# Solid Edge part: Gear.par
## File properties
Author: Admin
Template: SEER_ExtSpurGear.par
Last saved by: Admin
Revision: 3
Application: Solid Edge
Density: 7833.000 kg/m^3
Accuracy: 0.990
SEER_Parameters: SEERSG2#ER#4#ER#0.349065850398866#ER#0.003#ER#0.032#ER#0#ER#0.001#ER#0#ER#1#ER#1.2#ER#0.8#ER#10000#ER#1#ER#1#ER#30#ER#120#ER#0.0024#ER#0.0064#ER#0.01#ER#0.014#ER#0#ER#0#ER#6#ER#1000#ER#104.71975511966#ER#104.71975511966#ER#9.54#ER#9.54#ER#0.92#ER#1#ER#1#ER#1#ER#1#ER#0#ER#0#ER#1#ER#0#ER#0#ER#1#ER#0#ER#0#ER#0.08#ER#0.08#ER#0.008#ER#0.008#ER#0.025#ER#0.025#ER#0#ER#1140#ER#605#ER#0#ER#1140#ER#390#ER#11#ER#SweptProtrusion_1#ER#Pattern_1#ER#SweptProtrusion_1#ER#Pattern_1#ER##ER#E:\Project\3D\SoccerBot\Hardware\Pinion.par#ER#0#ER#0#ER#ExtrudedProtrusion_4#ER#ExtrudedCutout_5#ER#ExtrudedProtrusion_4#ER#ExtrudedCutout_5#ER#0#ER#1#ER#0#ER#0#ER#False#ER#0
Username: Admin
Material: Steel
Face Style: Steel
Fill Style: ANSI32(Steel)
Virtual Style: Machined steel
Coef. of Thermal Exp: 1.3e-05
Thermal Conductivity: 32.0
Specific Heat: 481.0
Modulus of Elasticity: 199947953000.0
Poission's Ratio: 0.29
Yield Stress: 262000766.0
Ultimate Stress: 358527364.0
Elongation: 0.0
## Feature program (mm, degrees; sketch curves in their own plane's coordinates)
sketch for "unnamed Protrusion 1" plane through (0, 0, 0) normal (0, 0, 1) x-axis (1, 0, 0)
  circle centre (0, 0) radius 5.5775
extrude "unnamed Protrusion 1" add finite 10 along +normal
sketch for "unnamed Cutout 1" plane through (0, 0, 10) normal (0, 0, 1) x-axis (0, 1, 0)
extrude "unnamed Cutout 1" cut through along -normal
swept protrusion "SweptProtrusion_1"
pattern "unnamed Pattern 1" of "SweptProtrusion_1"
swept protrusion "unnamed SweptProtrusion 1"
swept protrusion "unnamed SweptProtrusion 2"
swept protrusion "unnamed SweptProtrusion 3"
swept protrusion "unnamed SweptProtrusion 4"
swept protrusion "unnamed SweptProtrusion 5"
swept protrusion "unnamed SweptProtrusion 6"
swept protrusion "unnamed SweptProtrusion 7"
swept protrusion "unnamed SweptProtrusion 8"
swept protrusion "unnamed SweptProtrusion 9"
swept protrusion "unnamed SweptProtrusion 10"
swept protrusion "unnamed SweptProtrusion 11"
swept protrusion "unnamed SweptProtrusion 12"
swept protrusion "unnamed SweptProtrusion 13"
swept protrusion "unnamed SweptProtrusion 14"
swept protrusion "unnamed SweptProtrusion 15"
swept protrusion "unnamed SweptProtrusion 16"
swept protrusion "unnamed SweptProtrusion 17"
swept protrusion "unnamed SweptProtrusion 18"
swept protrusion "unnamed SweptProtrusion 19"
swept protrusion "unnamed SweptProtrusion 20"
sketch for "ExtrudedProtrusion_5" plane through (0, 0.024, 0) normal (0, 0, -1) x-axis (1, 0, 0)
  circle centre (0, 0.024) radius 7.095
extrude "ExtrudedProtrusion_5" add finite 1 along +normal
sketch for "ExtrudedCutout_6" plane through (0, 0.024, 0) normal (0, 0, -1) x-axis (1, 0, 0)
  circle centre (0, 0.024) radius 1.2
extrude "ExtrudedCutout_6" cut finite 21.5926 symmetric
base feature "unnamed BaseFeature 1"
sketch for "ExtrudedProtrusion_4" plane through (0, 0, 0) normal (0, 0, 1) x-axis (1, 0, 0)
  circle centre (0, 0) radius 6.2805
extrude "ExtrudedProtrusion_4" add finite 10 along +normal
sketch for "ExtrudedCutout_5" plane through (0, 0, 0) normal (0, 0, 1) x-axis (1, 0, 0)
  circle centre (0, 0) radius 6.2805
extrude "ExtrudedCutout_5" cut finite 10 along +normal
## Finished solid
Body 1: sheet body, 1 face, 2 edges, 0 vertices.
  Faces by surface: cylinder 1
  Edges by curve: circle 2
Body 2: solid body, 131 faces, 382 edges, 252 vertices.
  Faces by surface: spline 105, cylinder 23, plane 3
  Edges by curve: spline 168, circle 130, curve on surface 42, line 37, intersection 5
Bounding box of the edges (mm; curved faces can reach further): 14.190 x 14.190 x 11.000, from (-7.095, -7.095, -1) to (7.095, 7.095, 10).
Cylindrical faces by radius (mm): R1.2 x1, R5.5775 x21, R6.2805 x1, R7.095 x1
Planar faces by outward normal: +z 2, -z 1
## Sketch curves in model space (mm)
circle centre (0, 0, 0) radius 7.095
circle centre (0, 0, 0) radius 1.2
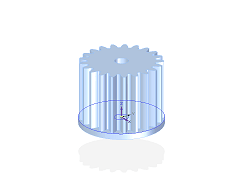
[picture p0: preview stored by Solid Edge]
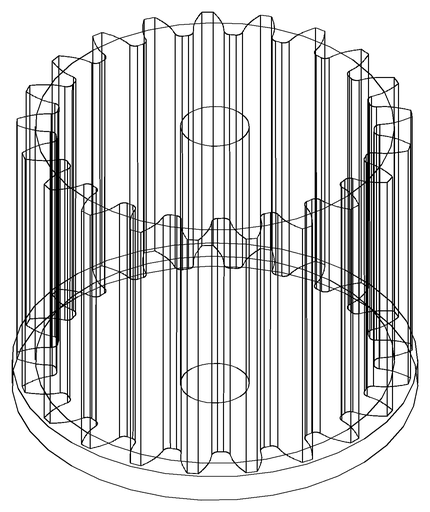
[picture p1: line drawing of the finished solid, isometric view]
